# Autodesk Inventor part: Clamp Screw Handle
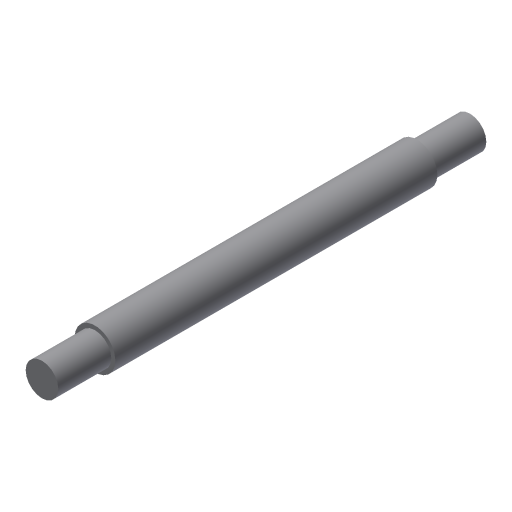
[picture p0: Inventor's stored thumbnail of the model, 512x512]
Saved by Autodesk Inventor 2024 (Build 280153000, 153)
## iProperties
Shininess: 77.0
Length Units: 11269
Angle Units: 11279
Time Units: 11290
Mass Units: 11283
Length Display Precision: 3
Angle Display Precision: 2
Compacted: True
Created: 2002-02
Part Number: Clamp Screw Handle
Document SubType Name: Modeling
Designer: ***
Density: 1 g/cm^3
Material: Generic
Appearance: Default
Density: 0.0
Volumn: 0.0
Area: 0.0
PropertySet Name: Model Information
Control State: 0
Master: False
Checked Out: False
Author: ***
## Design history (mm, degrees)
sketch "Sketch1"
  geometry: L1 (0, 105)-(4, 105); L2 (4, 105)-(4, 92); L3 (4, 92)-(5, 92); L4 (5, 92)-(5, 13); L5 (5, 13)-(4, 13); L6 (4, 13)-(4, 0); L7 (4, 0)-(0, 0); L8 (0, 0)-(0, 105)
  constraints: 16 end point, 5 parallel, 2 equal length, 1 collinear, 1 horizontal, 1 perpendicular
  dimensions: "d0" = 10 diameter of L4 L8; "d1" = 8 diameter of L2 L8; "d2" = 13 distance of L1.end L2.end; "d3" = 79 distance of L3.end L4.end
revolve "Revolution1" sketch "Sketch1" stored, may be unused: angle "d4" = 90 deg
body "Solid1"
